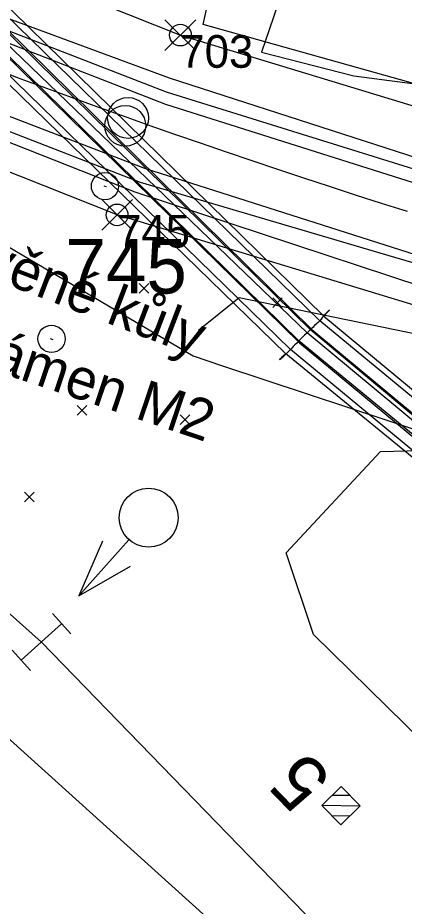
# Model space of a CAD drawing. Extents: x -800194 to -799078, y -1007177 to -1006597.
# Drawn here: x -799753.2 to -799739, y -1007007.87 to -1006975.25 of the extents above; entities that cross this region are included whole.
import ezdxf

# ---------------------------------------------------------------- set-up
doc = ezdxf.new("R2010")
doc.units = 0
for name, color, linetype in [('02_Osa_koleje', 7, 'Continuous'), ('_návrh', 7, 'Continuous'), ('_Vrstva 7 - Přesunutá', 7, 'Continuous'), ('Obvod stavby', 7, 'Continuous'), ('Vrstva 11', 7, 'Continuous'), ('Vrstva 16', 7, 'Continuous'), ('Vrstva 17', 7, 'Continuous'), ('Vrstva 18', 7, 'Continuous'), ('Vrstva 3', 7, 'Continuous'), ('Vrstva 4', 7, 'Continuous'), ('Vrstva 49', 7, 'Continuous'), ('Vrstva 50', 7, 'Continuous'), ('Vrstva 55', 7, 'Continuous'), ('Vrstva 60', 7, 'Continuous'), ('Vrstva 7', 7, 'Continuous')]:
    doc.layers.add(name, color=color, linetype=linetype)

msp = doc.modelspace()

# ---------------------------------------------------------------- linework, layer by layer
at = {"layer": '02_Osa_koleje'}
msp.add_lwpolyline([(-799754.025, -1006977.142), (-799753.088, -1006977.491), (-799752.149, -1006977.838), (-799751.21, -1006978.181), (-799750.27, -1006978.521), (-799749.328, -1006978.858), (-799748.386, -1006979.192), (-799747.442, -1006979.523), (-799746.497, -1006979.85), (-799745.551, -1006980.175), (-799744.604, -1006980.496), (-799743.656, -1006980.814), (-799742.707, -1006981.129), (-799741.757, -1006981.441), (-799740.806, -1006981.749), (-799739.853, -1006982.055), (-799738.9, -1006982.357)], dxfattribs=at)
at = {"layer": '_návrh'}
for points in [[(-799821.595, -1006948.007), (-799811.064, -1006954.324), (-799803.753, -1006958.707), (-799793.935, -1006964.581), (-799784.224, -1006971.671), (-799782.913, -1006972.63), (-799767.418, -1006984.719), (-799752.333, -1006998.173), (-799735.027, -1007015.997), (-799721.623, -1007030.81), (-799713.555, -1007039.726), (-799713.111, -1007040.218)], [(-799820.755, -1006954.001), (-799803.004, -1006964.743), (-799786.682, -1006975.322), (-799769.882, -1006987.807), (-799754.745, -1007000.643), (-799736.311, -1007017.261), (-799721.623, -1007030.81)]]:
    msp.add_lwpolyline(points, dxfattribs=at)
at = {"layer": '_Vrstva 7 - Přesunutá'}
msp.add_circle((-799749.152, -1006978.93), 0.75, dxfattribs=at)
at = {"layer": 'Obvod stavby'}
for p, q in [((-799747.794, -1006976.455), (-799746.663, -1006975.323)), ((-799747.794, -1006975.323), (-799746.663, -1006976.455)), ((-799750.12, -1006983.057), (-799748.989, -1006981.926)), ((-799750.12, -1006981.926), (-799748.989, -1006983.057))]:
    msp.add_line(p, q, dxfattribs=at)
msp.add_lwpolyline([(-799664.426, -1006999.087), (-799684.601, -1006997.477), (-799704.619, -1006994.49), (-799724.386, -1006990.14), (-799749.554, -1006982.491), (-799772.102, -1006973.528), (-799780.707, -1006969.551), (-799777.674, -1006963.242), (-799769.263, -1006967.129), (-799747.228, -1006975.889), (-799722.648, -1006983.359), (-799703.35, -1006987.606), (-799683.806, -1006990.523), (-799664.228, -1006992.091)], dxfattribs=at)
for centre in [(-799747.228, -1006975.889), (-799749.554, -1006982.491)]:
    msp.add_circle(centre, 0.4, dxfattribs=at)
at = {"layer": 'Vrstva 11'}
for p, q in [((-799740.986, -1007003.813), (-799741.655, -1007003.803)), ((-799740.621, -1007004.194), (-799742.031, -1007004.173)), ((-799741.001, -1007004.563), (-799741.662, -1007004.553))]:
    msp.add_line(p, q, dxfattribs=at)
msp.add_lwpolyline([(-799741.336, -1007004.888), (-799742.033, -1007004.171), (-799741.316, -1007003.474), (-799740.619, -1007004.191)], close=True, dxfattribs=at)
at = {"layer": 'Vrstva 16'}
for points in [[(-799726.857, -1006999.659), (-799736.574, -1006991.623), (-799742.439, -1006986.725), (-799754.518, -1006974.879), (-799763.734, -1006965.993), (-799777.293, -1006954.374), (-799779.945, -1006952.099), (-799783.722, -1006948.693)], [(-799783.708, -1006948.669), (-799779.9, -1006952.065), (-799777.252, -1006954.333), (-799763.672, -1006965.935), (-799754.476, -1006974.829), (-799742.393, -1006986.703), (-799736.524, -1006991.578), (-799726.778, -1006999.642)], [(-799784.356, -1006949.5), (-799780.347, -1006952.62), (-799777.716, -1006954.827), (-799764.168, -1006966.436), (-799754.935, -1006975.363), (-799742.857, -1006987.188), (-799736.94, -1006992.081), (-799727.324, -1007000.028)], [(-799727.258, -1006999.988), (-799736.887, -1006992.032), (-799742.859, -1006987.132), (-799754.894, -1006975.337), (-799764.135, -1006966.374), (-799777.698, -1006954.783), (-799780.331, -1006952.581), (-799784.321, -1006949.462)], [(-799779.465, -1006951.506), (-799778.251, -1006952.583), (-799776.738, -1006953.884), (-799763.224, -1006965.504), (-799753.999, -1006974.421), (-799741.964, -1006986.204), (-799736.168, -1006991.012), (-799728.577, -1006997.215), (-799726.123, -1006999.163)], [(-799727.952, -1007000.326), (-799729.82, -1006998.717), (-799737.37, -1006992.486), (-799743.358, -1006987.594), (-799755.401, -1006975.883), (-799764.592, -1006966.926), (-799778.073, -1006955.449), (-799779.598, -1006954.142), (-799780.843, -1006953.125)]]:
    msp.add_lwpolyline(points, dxfattribs=at)
at = {"layer": 'Vrstva 17'}
for points in [[(-799726.806, -1006975.491), (-799728.174, -1006980.607), (-799746.39, -1006975.498), (-799745.242, -1006970.318), (-799744.263, -1006965.815), (-799756.721, -1006963.941)], [(-799746.564, -1006986.717), (-799745.074, -1006985.521), (-799738.458, -1006986.883), (-799728.745, -1006990.03), (-799724.988, -1006990.685)]]:
    msp.add_lwpolyline(points, dxfattribs=at)
at = {"layer": 'Vrstva 18'}
for points in [[(-799776.738, -1006953.884), (-799763.224, -1006965.504), (-799753.999, -1006974.421), (-799741.964, -1006986.204), (-799736.168, -1006991.012)], [(-799728.689, -1006997.417), (-799736.272, -1006991.186), (-799742.111, -1006986.385), (-799754.178, -1006974.631), (-799763.368, -1006965.72), (-799777.061, -1006954.31)], [(-799736.701, -1006991.694), (-799742.573, -1006986.82), (-799754.68, -1006975.182), (-799763.887, -1006966.256), (-799777.391, -1006954.732)], [(-799729.664, -1006998.596), (-799737.245, -1006992.341), (-799743.186, -1006987.438), (-799755.222, -1006975.72), (-799764.444, -1006966.802), (-799777.959, -1006955.323)], [(-799737.37, -1006992.486), (-799743.358, -1006987.594), (-799755.401, -1006975.883), (-799764.592, -1006966.926), (-799778.073, -1006955.449)]]:
    msp.add_lwpolyline(points, dxfattribs=at)
for centre, major_axis, ratio, start_param, end_param in [((-799742.548, -1006987.401), (-0.826, -1.378), 0.12501, 3.399125, 3.961351), ((-799742.949, -1006987.371), (1.204, 1.399), 0.014573, 5.978594, 6.879596), ((-799742.617, -1006986.915), (0.711, 0.695), 0.037234, 0.742353, 2.460401), ((-799742.2, -1006986.605), (-1.386, -1.202), 0.01146, 5.69132, 6.569057), ((-799742.474, -1006986.496), (1.116, 1.298), 0.059378, 3.418673, 3.953091)]:
    msp.add_ellipse(centre, major_axis=major_axis, ratio=ratio, start_param=start_param, end_param=end_param, dxfattribs=at)
at = {"layer": 'Vrstva 3'}
for p, q in [((-799750.958, -1006996.476), (-799749.12, -1006994.416)), ((-799751.927, -1006997.131), (-799751.256, -1006997.873)), ((-799751.592, -1006997.502), (-799753.074, -1006998.844)), ((-799753.41, -1006998.473), (-799752.739, -1006999.215))]:
    msp.add_line(p, q, dxfattribs=at)
msp.add_lwpolyline([(-799750.095, -1006994.472), (-799750.958, -1006996.476), (-799749.065, -1006995.39)], dxfattribs=at)
msp.add_circle((-799748.396, -1006993.609), 1.084, dxfattribs=at)
at = {"layer": 'Vrstva 4'}
for points in [[(-799766.319, -1006970.565), (-799760.949, -1006972.542), (-799747.638, -1006977.46), (-799730.549, -1006982.982), (-799710.066, -1006987.578), (-799704.728, -1006988.346), (-799693.001, -1006990.373), (-799682.434, -1006991.64), (-799671.27, -1006992.619), (-799659.31, -1006993.026), (-799648.69, -1006993.125), (-799637.398, -1006992.704), (-799625.913, -1006992.175), (-799614.965, -1006990.831), (-799603.911, -1006989.312), (-799592.728, -1006987.172), (-799581.605, -1006984.547), (-799570.583, -1006981.598), (-799559.909, -1006978.216), (-799542.956, -1006972.25), (-799531.79, -1006967.658), (-799521.285, -1006962.191), (-799511.236, -1006957.129)], [(-799779.678, -1006964.304), (-799766.319, -1006970.565), (-799761.253, -1006973.176), (-799747.77, -1006978.421), (-799730.774, -1006983.8), (-799710.333, -1006988.709), (-799704.916, -1006989.741), (-799693.131, -1006991.407), (-799682.585, -1006992.929), (-799671.325, -1006993.879), (-799659.363, -1006994.45), (-799648.66, -1006994.501), (-799637.23, -1006994.127), (-799626.066, -1006993.335), (-799614.788, -1006992.17), (-799603.669, -1006990.506), (-799592.467, -1006988.452), (-799581.281, -1006985.916), (-799570.22, -1006982.998), (-799559.296, -1006979.606), (-799542.375, -1006973.485), (-799531.236, -1006968.774), (-799520.48, -1006963.762), (-799510.394, -1006958.536)], [(-799776.864, -1006969.085), (-799770.965, -1006971.646), (-799761.91, -1006975.649), (-799748.544, -1006980.777), (-799731.457, -1006986.215), (-799711.132, -1006991.054), (-799705.482, -1006992.16), (-799693.53, -1006994.084), (-799682.801, -1006995.384), (-799671.514, -1006996.319), (-799659.449, -1006996.851), (-799648.588, -1006996.949), (-799637.262, -1006996.573), (-799625.835, -1006995.773), (-799614.546, -1006994.586), (-799603.199, -1006992.945), (-799591.969, -1006990.857), (-799580.647, -1006988.335), (-799569.534, -1006985.311), (-799558.557, -1006981.947), (-799541.405, -1006975.739), (-799530.263, -1006971.071), (-799519.455, -1006966), (-799509.248, -1006960.724)], [(-799776.864, -1006969.085), (-799771.262, -1006971.982), (-799762.131, -1006976.093), (-799748.706, -1006981.286), (-799731.51, -1006986.353), (-799711.222, -1006991.459), (-799705.527, -1006992.587), (-799693.582, -1006994.543), (-799682.85, -1006995.904), (-799671.5, -1006996.805), (-799659.556, -1006997.356), (-799648.616, -1006997.341), (-799637.276, -1006997.071), (-799625.828, -1006996.297), (-799614.43, -1006995.109), (-799603.18, -1006993.475), (-799591.849, -1006991.264), (-799580.564, -1006988.698), (-799569.449, -1006985.746), (-799558.385, -1006982.386), (-799541.268, -1006976.227), (-799530.102, -1006971.505), (-799519.398, -1006966.36), (-799509.087, -1006961.127)], [(-799779.011, -1006963.023), (-799770.632, -1006967.944), (-799766.319, -1006970.565), (-799761.021, -1006972.82), (-799747.748, -1006977.966), (-799730.719, -1006983.271), (-799710.195, -1006988.108), (-799704.765, -1006989.181), (-799693.072, -1006990.965), (-799682.554, -1006992.238), (-799671.266, -1006993.222), (-799659.388, -1006993.765), (-799648.658, -1006993.824), (-799637.385, -1006993.531), (-799625.769, -1006992.728), (-799614.9, -1006991.542), (-799603.91, -1006989.963), (-799592.572, -1006987.892), (-799581.421, -1006985.419), (-799570.327, -1006982.332), (-799559.429, -1006979.066), (-799542.601, -1006973.013), (-799531.454, -1006968.25), (-799520.744, -1006963.214)], [(-799776.864, -1006969.085), (-799771.693, -1006972.522), (-799762.217, -1006976.394), (-799748.898, -1006981.647), (-799733.68, -1006986.66), (-799728.795, -1006987.945), (-799711.349, -1006992.599), (-799705.744, -1006994.116), (-799693.689, -1006996.09), (-799689.347, -1006996.226), (-799688.222, -1006996.296), (-799683.105, -1006997.407), (-799671.667, -1006998.275)]]:
    msp.add_lwpolyline(points, dxfattribs=at)
at = {"layer": 'Vrstva 49'}
for p, q in [((-799748.745, -1006985.013), (-799748.391, -1006985.367)), ((-799748.745, -1006985.367), (-799748.391, -1006985.013)), ((-799743.837, -1006985.534), (-799743.483, -1006985.888)), ((-799743.837, -1006985.888), (-799743.483, -1006985.534)), ((-799751.015, -1006989.494), (-799750.661, -1006989.848)), ((-799751.015, -1006989.848), (-799750.661, -1006989.494)), ((-799747.241, -1006989.831), (-799746.887, -1006990.185)), ((-799747.241, -1006990.185), (-799746.887, -1006989.831)), ((-799752.956, -1006992.672), (-799752.602, -1006993.026)), ((-799752.956, -1006993.026), (-799752.602, -1006992.672))]:
    msp.add_line(p, q, dxfattribs=at)
msp.add_lwpolyline([(-799733.039, -1007005.939), (-799736.26, -1007003.86), (-799742.34, -1006997.896), (-799743.342, -1006994.901), (-799739.871, -1006991.182), (-799734.968, -1006991.052), (-799728.642, -1006990.92), (-799723.01, -1006991.966), (-799716.141, -1006994.243), (-799710.319, -1006994.817)], dxfattribs=at)
at = {"layer": 'Vrstva 50'}
msp.add_line((-799752.008, -1006987.026), (-799751.914, -1006987.06), dxfattribs=at)
msp.add_circle((-799751.961, -1006987.043), 0.5, dxfattribs=at)
at = {"layer": 'Vrstva 55'}
for points in [[(-799785.23, -1006937.71), (-799791.69, -1006959.99), (-799791.97, -1006960.97), (-799746.76, -1006987.67), (-799745.68, -1006988.03), (-799733.28, -1006992.13)], [(-799741.57, -1006968.68), (-799744.25, -1006976.52), (-799740.85, -1006977.38), (-799729.15, -1006978.91), (-799727.37, -1006976.97)]]:
    msp.add_lwpolyline(points, dxfattribs=at)
at = {"layer": 'Vrstva 60'}
for p, q in [((-799747.228, -1006975.889), (-799747.228, -1006975.889)), ((-799749.554, -1006982.491), (-799749.554, -1006982.491))]:
    msp.add_line(p, q, dxfattribs=at)
at = {"layer": 'Vrstva 7'}
msp.add_line((-799750.046, -1006981.42), (-799749.952, -1006981.454), dxfattribs=at)
for centre, radius in [((-799749.254, -1006979.22), 0.75), ((-799749.999, -1006981.437), 0.5)]:
    msp.add_circle(centre, radius, dxfattribs=at)

# ---------------------------------------------------------------- texts
at = {"layer": 'Obvod stavby'}
msp.add_text('745', height=2, rotation=360, dxfattribs=at).set_placement((-799751.454, -1006985.375))
at = {"layer": 'Vrstva 11'}
msp.add_text('5', height=2, rotation=134.1552, dxfattribs=at).set_placement((-799741.611, -1007003.165))
at = {"layer": 'Vrstva 50'}
for s, rotation, p in [('dřevěné kůly', 339.0461, (-799757.288, -1006983.641)), ('kámen M2', 341.4135, (-799755.173, -1006987.846))]:
    msp.add_text(s, height=1.5, rotation=rotation, dxfattribs=at).set_placement(p)
at = {"layer": 'Vrstva 60'}
for s, p in [('703', (-799747.228, -1006977.089)), ('745', (-799749.554, -1006983.691))]:
    msp.add_text(s, height=1.2, dxfattribs=at).set_placement(p)

doc.saveas('drawing.dxf')
